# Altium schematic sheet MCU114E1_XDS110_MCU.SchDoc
size 431 x 279 mm; Date: Not shown in title block; ApprovedBy: Not shown in title block; CheckedBy: Not shown in title block; Author: Not shown in title block; CompanyName: Not shown in title block; Engineer: Not shown in title block; Organization: Not shown in title block; Address1: Not shown in title block; Address2: Not shown in title block; Address3: Not shown in title block; Address4: Not shown in title block; DocumentNumber: 9; Revision: Use project parameter SCH_Rev; SheetNumber: 9; SheetTotal: 10; PageSetup: Record=PageOptions¦CenterHorizontal=True¦CenterVertical=True¦PrintScale=1.00¦XCorrection=1.00¦YCorrection=1.00¦PrintKind=0¦BorderSize=5000000¦LeftOffset=0¦BottomOffset=0¦Orientation=2¦PaperLength=1000¦PaperWidth=1000¦Scale=100¦PaperSource=15¦PrintQuality=600¦MediaType=1¦DitherType=10¦PaperKind=Letter¦PrintScaleMode=1
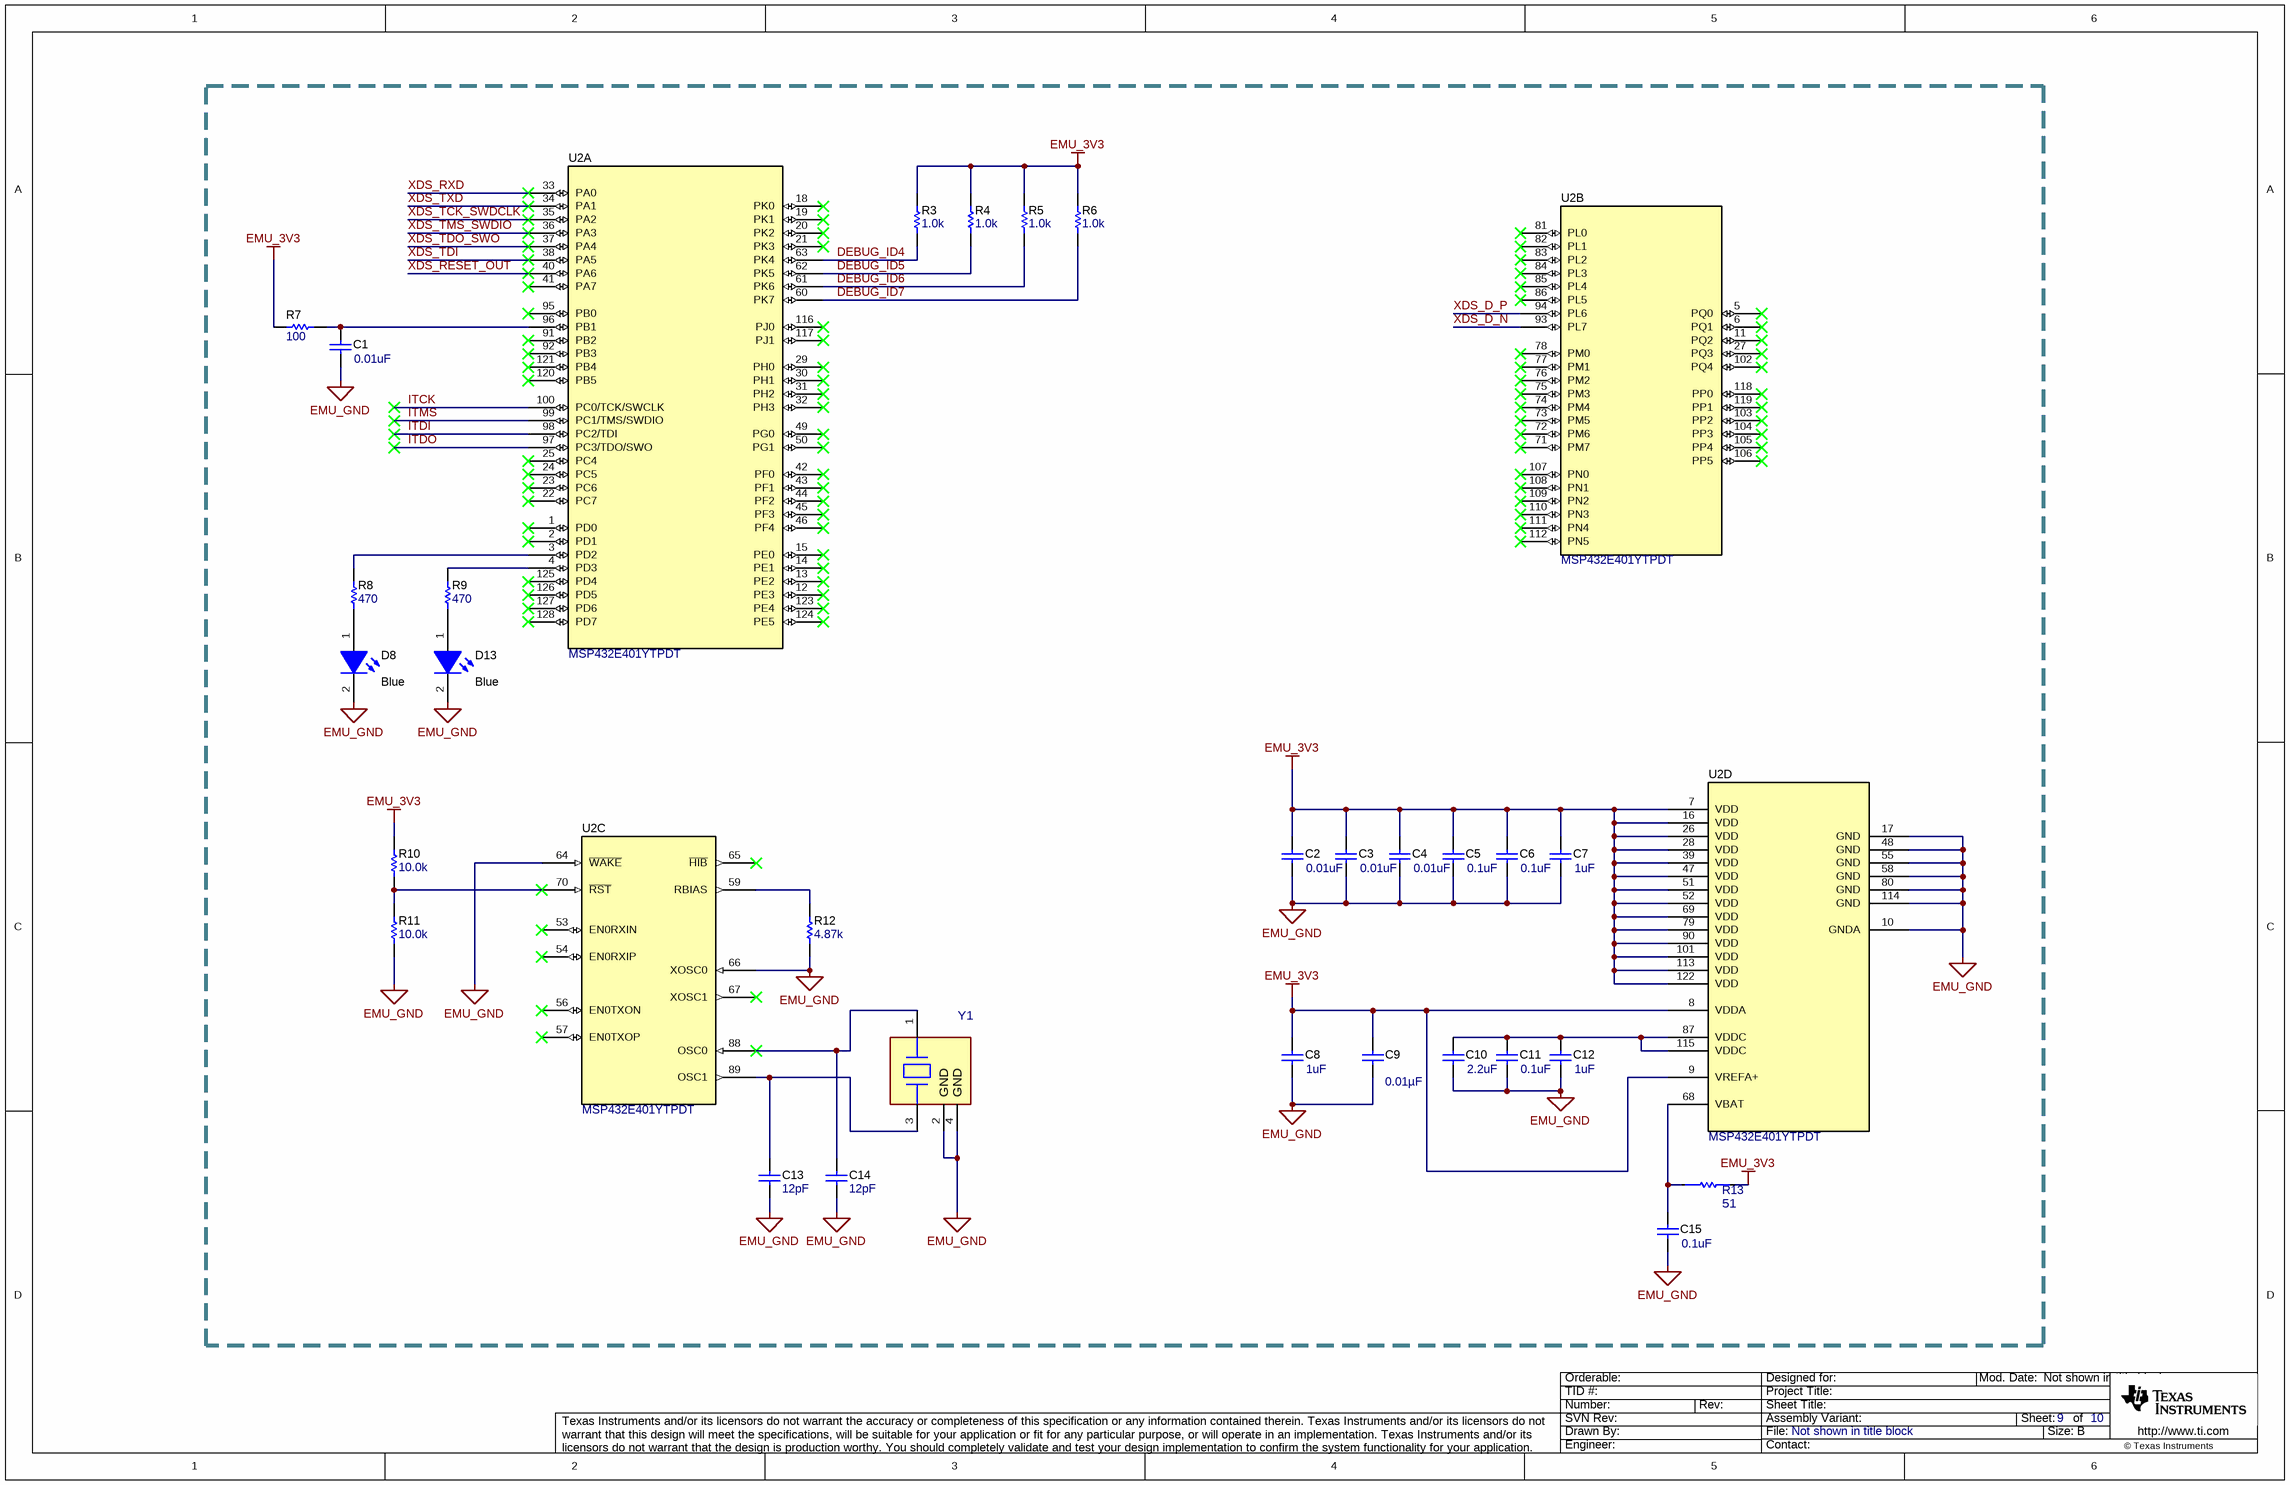
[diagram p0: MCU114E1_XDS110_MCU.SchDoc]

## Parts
C1  ValueDisplayed: 0.01uF  [0402]  (hidden comment: 885012205031)
C2  ValueDisplayed: 0.01uF  [0402]  (hidden comment: 885012205031)
C3  ValueDisplayed: 0.01uF  [0402]  (hidden comment: 885012205031)
C4  ValueDisplayed: 0.01uF  [0402]  (hidden comment: 885012205031)
C5  ValueDisplayed: 0.1uF  [0402]  (hidden comment: GRM155R60J104KA01D)
C6  ValueDisplayed: 0.1uF  [0402]  (hidden comment: GRM155R60J104KA01D)
C7  ValueDisplayed: 1uF  [0402]  (hidden comment: 885012105012)
C8  ValueDisplayed: 1uF  [0402]  (hidden comment: 885012105012)
C9  ValueDisplayed: 0.01µF  [0402]  (hidden comment: CL05B103KA5NNNC)
C10  ValueDisplayed: 2.2uF  [0402]  (hidden comment: 885012105013)
C11  ValueDisplayed: 0.1uF  [0402]  (hidden comment: GRM155R60J104KA01D)
C12  ValueDisplayed: 1uF  [0402]  (hidden comment: 885012105012)
C13  ValueDisplayed: 12pF  [0402]  (hidden comment: CL05C120JB5NNNC)
C14  ValueDisplayed: 12pF  [0402]  (hidden comment: CL05C120JB5NNNC)
C15  ValueDisplayed: 0.1uF  [0402]  (hidden comment: GRM155R60J104KA01D)
D8  value Blue  [LTST-C170TBKT_Blue]  (hidden comment: LTST-C170TBKT)
D13  value Blue  [LTST-C170TBKT_Blue]  (hidden comment: LTST-C170TBKT)
R3  ValueDisplayed: 1.0k  [0402]  (hidden comment: CRCW04021K00JNED)
R4  ValueDisplayed: 1.0k  [0402]  (hidden comment: CRCW04021K00JNED)
R5  ValueDisplayed: 1.0k  [0402]  (hidden comment: CRCW04021K00JNED)
R6  ValueDisplayed: 1.0k  [0402]  (hidden comment: CRCW04021K00JNED)
R7  ValueDisplayed: 100  [0402]  (hidden comment: CRCW0402100RJNED)
R8  ValueDisplayed: 470  [0402]  (hidden comment: ERJ-2RKF4700X)
R9  ValueDisplayed: 470  [0402]  (hidden comment: ERJ-2RKF4700X)
R10  ValueDisplayed: 10.0k  [0402]  (hidden comment: AC0402FR-0710KL)
R11  ValueDisplayed: 10.0k  [0402]  (hidden comment: AC0402FR-0710KL)
R12  ValueDisplayed: 4.87k  [0402]  (hidden comment: CRCW04024K87FKED)
R13  51  [FP-RT0402FRE0751RL_0402-MFG]
U2  MSP432E401YTPDT  [PDT0128A]  (parts A,B,C,D of 4)
Y1  830064296  [FP-830064296_SMT4_3MM4_2MM7-MFG]  (value not drawn)

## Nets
EMU_3V3: C2.1 C3.1 C4.1 C5.1 C6.1 C7.1 C8.1 C9.1 R3.2 R4.2 R5.2 R6.2 R7.1 R10.2 R13.2 U2.7(VDD) U2.8(VDDA) U2.9(VREFA+) U2.16(VDD) U2.26(VDD) U2.28(VDD) U2.39(VDD) U2.47(VDD) U2.51(VDD) U2.52(VDD) U2.69(VDD) U2.79(VDD) U2.90(VDD) U2.101(VDD) U2.113(VDD) U2.122(VDD)
EMU_GND: C1.2 C2.2 C3.2 C4.2 C5.2 C6.2 C7.2 C8.2 C9.2 C10.2 C11.2 C12.2 C13.2 C14.2 C15.2 D8.2(K) D13.2(K) R11.1 R12.1 U2.10(GNDA) U2.17(GND) U2.48(GND) U2.55(GND) U2.58(GND) U2.64(~{WAKE}) U2.66(XOSC0) U2.80(GND) U2.114(GND) Y1.2(GND) Y1.4(GND)
DEBUG_ID4: R3.1 U2.63(PK4)
DEBUG_ID5: R4.1 U2.62(PK5)
DEBUG_ID6: R5.1 U2.61(PK6)
DEBUG_ID7: R6.1 U2.60(PK7)
ITCK: U2.100(PC0/TCK/SWCLK)
ITDI: U2.98(PC2/TDI)
ITDO: U2.97(PC3/TDO/SWO)
ITMS: U2.99(PC1/TMS/SWDIO)
XDS_D_N: U2.93(PL7)
XDS_D_P: U2.94(PL6)
XDS_RESET_OUT: U2.40(PA6)
XDS_RXD: U2.33(PA0)
XDS_TCK_SWDCLK: U2.35(PA2)
XDS_TDI: U2.38(PA5)
XDS_TDO_SWO: U2.37(PA4)
XDS_TMS_SWDIO: U2.36(PA3)
XDS_TXD: U2.34(PA1)
NetC1_1: C1.1 R7.2 U2.96(PB1)
NetC10_1: C10.1 C11.1 C12.1 U2.87(VDDC) U2.115(VDDC)
NetC13_1: C13.1 U2.89(OSC1) Y1.3(2_Crystal)
NetC14_1: C14.1 U2.88(OSC0) Y1.1(1_Crystal)
NetC15_1: C15.1 R13.1 U2.68(VBAT)
NetD8_1: D8.1(A) R8.1
NetD13_1: D13.1(A) R9.1
NetR8_2: R8.2 U2.3(PD2)
NetR9_2: R9.2 U2.4(PD3)
NetR10_1: R10.1 R11.2 U2.70(~{RST})
NetR12_2: R12.2 U2.59(RBIAS)

Not connected (* = marked no-connect by the designer): U2 1(PD0)* 2(PD1)* 5(PQ0)* 6(PQ1)* 11(PQ2)* 12(PE3)* 13(PE2)* 14(PE1)* 15(PE0)* 18(PK0)* 19(PK1)* 20(PK2)* 21(PK3)* 22(PC7)* 23(PC6)* 24(PC5)* 25(PC4)* 27(PQ3)* 29(PH0)* 30(PH1)* 31(PH2)* 32(PH3)* 41(PA7)* 42(PF0)* 43(PF1)* 44(PF2)* 45(PF3)* 46(PF4)* 49(PG0)* 50(PG1)* 53(EN0RXIN)* 54(EN0RXIP)* 56(EN0TXON)* 57(EN0TXOP)* 65(~{HIB})* 67(XOSC1)* 71(PM7)* 72(PM6)* 73(PM5)* 74(PM4)* 75(PM3)* 76(PM2)* 77(PM1)* 78(PM0)* 81(PL0)* 82(PL1)* 83(PL2)* 84(PL3)* 85(PL4)* 86(PL5)* 91(PB2)* 92(PB3)* 95(PB0)* 102(PQ4)* 103(PP2)* 104(PP3)* 105(PP4)* 106(PP5)* 107(PN0)* 108(PN1)* 109(PN2)* 110(PN3)* 111(PN4)* 112(PN5)* 116(PJ0)* 117(PJ1)* 118(PP0)* 119(PP1)* 120(PB5)* 121(PB4)* 123(PE4)* 124(PE5)* 125(PD4)* 126(PD5)* 127(PD6)* 128(PD7)*

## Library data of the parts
C1-C4 = CMP-0006227-2: CAP, CERM, 0.01 uF, 16 V, +/- 10%, X7R, 0402; Manufacturer: Wurth Elektronik; TaMin_C: -55°C; Polarized: N; SizeAreaWB_mm2: 3; Value1: Unknown; U/M: EA; Value: 0.01uF; TaMax_C: 125°C; SizeZ_mm: 0.6; SizeX_mm: 1; SizeY_mm: 0.5; Value2: 16V; Cap_F: 10nF; AEC Category: Q200
C5 C6 C11 C15 = CMP-0006531-2: CAP, CERM, 0.1 uF, 6.3 V, +/- 10%, X5R, 0402; Manufacturer: MuRata; TaMin_C: -55°C; Polarized: N; SizeAreaWB_mm2: 3; Value1: Unknown; U/M: EA; Value: 0.1uF; TaMax_C: 85°C; SizeZ_mm: 0.6; SizeX_mm: 1; SizeY_mm: 0.5; Value2: 6.3V; Cap_F: 100nF; AEC Category: Q200
C7 C8 C12 = CMP-0064924-2: CAP, CERM, 1 uF, 10 V,+/- 20%, X5R, 0402; Manufacturer: Wurth Elektronik; TaMin_C: -55°C; Polarized: N; SizeAreaWB_mm2: 3; Value1: Unknown; U/M: EA; Value: 1uF; TaMax_C: 85°C; SizeZ_mm: 0.6; SizeX_mm: 1; SizeY_mm: 0.5; Value2: 10V; Cap_F: 1µF; AEC Category: Q200
C9 = CMP-0860561-1: CAP, CERM, 0.01 µF, 25 V,+/- 10%, X7R, 0402; Manufacturer: Samsung Electro-Mechanics; U/M: EA; SizeArea_mm2: 0.5; Value: 0.01uF; TaMin_C: -55°C; VDC_V: 25V; SizeZ_mm: 0.6; Polarized: N; SizeX_mm: 1; TaMax_C: 125°C; SizeAreaWB_mm2: 3; Cap_F: 10nF; AEC Category: Q200
C10 = CMP-0006222-2: CAP, CERM, 2.2 uF, 10 V, +/- 20%, X5R, 0402; Manufacturer: Wurth Elektronik; TaMin_C: -55°C; Polarized: N; SizeAreaWB_mm2: 3; Value1: Unknown; U/M: EA; Value: 2.2uF; TaMax_C: 85°C; SizeZ_mm: 0.6; SizeX_mm: 1; SizeY_mm: 0.5; Value2: 10V; Cap_F: 2.2µF; AEC Category: Q200
C13 C14 = CMP-0006345-2: CAP, CERM, 12 pF, 50 V, +/- 5%, C0G/NP0, 0402; Manufacturer: Samsung Electro-Mechanics; Polarized: N; Value: 12pF; U/M: EA; Value1: Unknown; VDC_V: 50V; TaMin_C: -55°C; TaMax_C: 125°C; SizeArea_mm2: 0.5; SizeAreaWB_mm2: 3; SizeX_mm: 1; SizeZ_mm: 0.6; AEC Category: Q200
D8 D13 = CMP-0002889-2: LED, Blue, SMD; Manufacturer: Lite-On; Type: AlInGaP; Vf_V: 3.3V; Io_A: 20mA; Value1: W
R3-R6 = CMP-0026852-3: RES, 1.0 k, 5%, 0.063 W, AEC-Q200 Grade 0, 0402; Manufacturer: Vishay-Dale; Power_W: 63mW; TempCo: 200 ppm/C; Value_Code: 1k00; Value: 1.0k; EIA_Code: E24; Res_ohm: 1k; SizeX_mm: 1; SizeY_mm: 0.5; SizeZ_mm: 0.6; Value2: 0.063W; AEC Qualified: Y; VDC_V: 50V; AEC Category: Q200; AEC Grade: 0
R7 = CMP-0026824-3: RES, 100, 5%, 0.063 W, AEC-Q200 Grade 0, 0402; Manufacturer: Vishay-Dale; Power_W: 63mW; TempCo: 200 ppm/C; Value_Code: 100R; Value: 100; EIA_Code: E24; SizeX_mm: 1; SizeY_mm: 0.5; SizeZ_mm: 0.6; Value2: 0.063W; AEC Qualified: Y; VDC_V: 50V; AEC Category: Q200; AEC Grade: 0
R8 R9 = CMP-0026699-1: RES, 470, 1%, 0.1 W, AEC-Q200 Grade 0, 0402; Manufacturer: Panasonic; Value: 470; Value_Code: 470R; Power_W: 100mW; Value2: 0.1W; VDC_V: 50V; TempCo: 100 ppm/C; SizeArea_mm2: 0.5; SizeX_mm: 1; SizeZ_mm: 0.6; U/M: EA; AEC Category: Q200; AEC Qualified: Y; AEC Grade: 0
R10 R11 = CMP-0077731-1: RES, 10.0 k, 1%, 0.063 W, AEC-Q200 Grade 0, 0402; Manufacturer: Yageo America; Power_W: 63mW; TempCo: 100 ppm/C; Value_Code: 10k0; U/M: EA; Value: 10.0k; EIA_Code: E96; Res_ohm: 10k; SizeX_mm: 1.0; SizeY_mm: 0.5; SizeZ_mm: 0.6; Value2: 0.063W; AEC Qualified: Y; VDC_V: 50V; AEC Grade: 0; AEC Category: Q200
R12 = CMP-0026413-2: RES, 4.87 k, 1%, 0.063 W, AEC-Q200 Grade 0, 0402; Manufacturer: Vishay-Dale; Power_W: 63mW; TempCo: 100 ppm/C; Value_Code: 4k87; Value: 4.87k; EIA_Code: E96; SizeX_mm: 1; SizeY_mm: 0.5; SizeZ_mm: 0.6; Value2: 0.063W; AEC Qualified: Y; VDC_V: 50V; AEC Category: Q200; AEC Grade: 0
R13 = CMP-0092664-1: 51 Ohms ±1% 0.063W, 1/16W Chip Resistor 0402 (1005 Metric) - Thin Film; PartNumber: RT0402FRE0751RL; Manufacturer: Yageo; VDC_V: 50V; AEC Qualified: No; Power_W: 63mW; TempCo: 50ppm/°C; SizeZ_mm: 0.35mm
U2 = CMP-0077953-1: MSP432E401YTPDT, PDT0128A (TQFP-128); Alternate PartNumber: MSP432E401YTPDTR; Alternate Manufacturer: Texas Instruments; SizeAreaWB_mm2: 324; SizeZ_mm: 1.2; SizeX_mm: 16; SizeArea_mm2: 256; CompType: IC; AEC Qualified: N; AEC Category: Q200
Y1 = CMP-0094478-1: Crystal 16 MHz ±20ppm Crystal 8pF 70 Ohms 4-SMD, No Lead; Manufacturer: Wurth; SizeZ_mm: 0.8mm; Frequency_Fixed: 16MHz; Esr: 70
